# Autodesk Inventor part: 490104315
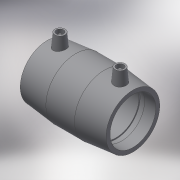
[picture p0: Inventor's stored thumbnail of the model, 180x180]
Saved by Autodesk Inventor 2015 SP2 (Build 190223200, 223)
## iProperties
Created: 2017-06
Part Number: 490104315
Material: Generic
Description: PLASSON COUPLER 315-315
Document SubType Name: Modeling
Designer: KIM
Mass: 9387.17 g
Surface Area: 6996.04 cm^2
Volume: 9387.17 cm^3
Density: 1 g/cm^3
Appearance: Default
Author: KIM
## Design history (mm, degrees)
derived "490104.ipt"
feature "Solid1::490104.ipt"
tag "TaggingFeature1"
body "Solid1"
other parameters: "d0" = 282, "d1" = 315, "d2" = 387, "d3" = 139, "d4" = 94, "d5" = 348.3, "d6" = 299.25, "d7" = 315, "d8" = 168 deg, "d10" = 55.6, "d11" = 18.53333, "d13" = 282, "d14" = 17.6296, "d15" = 139, "d16" = 139, "d17" = 299.25, "d18" = 315, "d19" = 3.52592, "d20" = 168 deg, "d22" = 363.78, "d23" = 387, "d24" = 352.8666, "d25" = 135 deg, "d26" = 155.1, "d27" = 135 deg, "d29" = 184, "d30" = 14, "d31" = 98.7, "d34" = 5 deg, "d35" = 15, "d39" = 5 deg, "d41" = 4, "d42" = 14, "d43" = 0, "d45" = 4, "d46" = 14, "d47" = 0, "d48" = 3, "d49" = 0, "d50" = 3, "d51" = 0, "d52" = 40.31, "d53" = 10.0775, "d_" = 315, "L_" = 282, "L_1" = 139, "D_" = 387, "A_" = 184, "d_2" = 12
